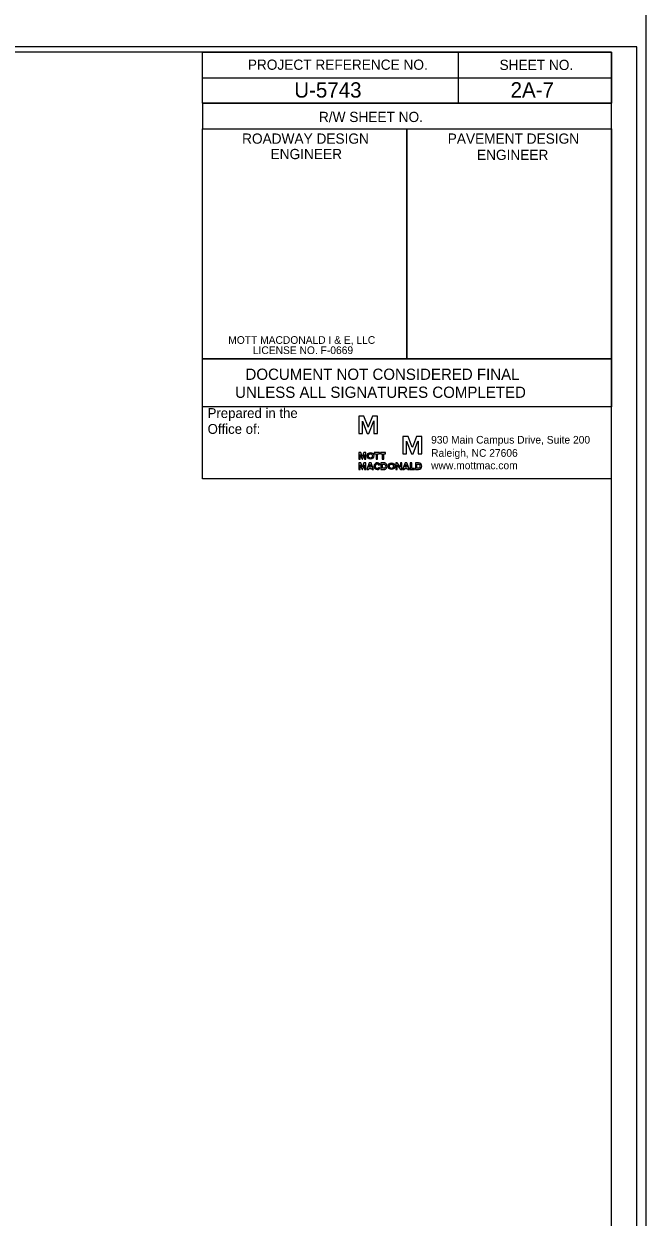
# Model space of a CAD drawing. Extents: x 1901670 to 1902225, y 193498 to 194278.
# Drawn here: x 1902103.8 to 1902134.2, y 193548.5 to 193606.9 of the extents above; entities that cross this region are included whole.
import ezdxf

# ---------------------------------------------------------------- set-up
doc = ezdxf.new("R2010")
doc.units = 0
for name, color, linetype in [('Old_Level_2', 7, 'Continuous'), ('Old_Level_42', 7, 'Continuous'), ('Old_Level_45', 7, 'Continuous'), ('Sheet Border Standard 30in CELL', 7, 'Continuous'), ('Sheet Data Field CELL', 7, 'Continuous'), ('Sheet Plot Border Inside CELL', 7, 'Continuous'), ('Sheet Plot Border Outside CELL', 7, 'Continuous'), ('Sheet Sticker Exception Certification CELL', 7, 'Continuous')]:
    doc.layers.add(name, color=color, linetype=linetype)

msp = doc.modelspace()

# ---------------------------------------------------------------- linework, layer by layer
at = {"layer": 'Old_Level_2'}
for p, q in [((1902120.437, 193587.699), (1902120.185, 193587.699)), ((1902120.185, 193587.699), (1902120.185, 193586.849)), ((1902120.642, 193587.174), (1902120.437, 193587.699)), ((1902120.853, 193587.699), (1902120.647, 193587.174)), ((1902121.105, 193587.699), (1902120.853, 193587.699)), ((1902121.105, 193586.849), (1902121.105, 193587.699)), ((1902120.364, 193586.849), (1902120.364, 193587.46)), ((1902120.364, 193587.46), (1902120.366, 193587.46)), ((1902120.366, 193587.46), (1902120.606, 193586.849)), ((1902120.642, 193587.166), (1902120.642, 193587.174)), ((1902120.647, 193587.166), (1902120.642, 193587.166)), ((1902120.647, 193587.174), (1902120.647, 193587.166)), ((1902120.684, 193586.849), (1902120.923, 193587.463)), ((1902120.923, 193587.463), (1902120.925, 193587.463)), ((1902120.925, 193587.463), (1902120.925, 193586.849)), ((1902120.185, 193586.849), (1902120.364, 193586.849)), ((1902120.606, 193586.849), (1902120.684, 193586.849)), ((1902120.925, 193586.849), (1902121.105, 193586.849)), ((1902122.598, 193586.709), (1902122.346, 193586.709)), ((1902122.346, 193586.709), (1902122.346, 193585.859)), ((1902122.525, 193585.859), (1902122.525, 193586.47)), ((1902122.525, 193586.47), (1902122.528, 193586.47)), ((1902122.528, 193586.47), (1902122.767, 193585.859)), ((1902122.803, 193586.184), (1902122.598, 193586.709)), ((1902123.014, 193586.709), (1902122.809, 193586.184)), ((1902122.845, 193585.859), (1902123.084, 193586.472)), ((1902123.266, 193586.709), (1902123.014, 193586.709)), ((1902123.084, 193586.472), (1902123.087, 193586.472)), ((1902123.087, 193586.472), (1902123.087, 193585.859)), ((1902123.266, 193585.859), (1902123.266, 193586.709)), ((1902120.281, 193585.919), (1902120.185, 193585.919)), ((1902120.185, 193585.919), (1902120.185, 193585.594)), ((1902120.252, 193585.594), (1902120.252, 193585.828)), ((1902120.252, 193585.828), (1902120.255, 193585.828)), ((1902120.252, 193585.828), (1902120.255, 193585.828)), ((1902120.255, 193585.828), (1902120.346, 193585.594)), ((1902120.361, 193585.716), (1902120.281, 193585.919)), ((1902120.442, 193585.919), (1902120.361, 193585.716)), ((1902120.377, 193585.594), (1902120.468, 193585.828)), ((1902120.538, 193585.919), (1902120.442, 193585.919)), ((1902120.468, 193585.828), (1902120.47, 193585.828)), ((1902120.468, 193585.828), (1902120.47, 193585.828)), ((1902120.468, 193585.828), (1902120.47, 193585.828)), ((1902120.47, 193585.828), (1902120.471, 193585.594)), ((1902120.538, 193585.594), (1902120.538, 193585.919)), ((1902120.538, 193585.594), (1902120.538, 193585.919)), ((1902122.346, 193585.859), (1902122.525, 193585.859)), ((1902122.767, 193585.859), (1902122.845, 193585.859)), ((1902122.803, 193586.176), (1902122.803, 193586.184)), ((1902122.809, 193586.176), (1902122.803, 193586.176)), ((1902122.809, 193586.184), (1902122.809, 193586.176)), ((1902123.087, 193585.859), (1902123.266, 193585.859)), ((1902120.185, 193585.594), (1902120.252, 193585.594)), ((1902120.281, 193585.414), (1902120.185, 193585.414)), ((1902120.185, 193585.414), (1902120.185, 193585.089)), ((1902120.252, 193585.089), (1902120.252, 193585.323)), ((1902120.252, 193585.323), (1902120.255, 193585.323)), ((1902120.255, 193585.323), (1902120.346, 193585.089)), ((1902120.361, 193585.211), (1902120.281, 193585.414)), ((1902120.346, 193585.594), (1902120.377, 193585.594)), ((1902120.442, 193585.414), (1902120.361, 193585.211)), ((1902120.377, 193585.089), (1902120.468, 193585.323)), ((1902120.538, 193585.414), (1902120.442, 193585.414)), ((1902120.468, 193585.323), (1902120.47, 193585.323)), ((1902120.47, 193585.323), (1902120.471, 193585.089)), ((1902120.471, 193585.594), (1902120.538, 193585.594)), ((1902120.538, 193585.089), (1902120.538, 193585.414)), ((1902121.221, 193585.156), (1902121.164, 193585.184)), ((1902121.221, 193585.156), (1902121.164, 193585.184)), ((1902121.172, 193585.308), (1902121.229, 193585.335)), ((1902121.172, 193585.308), (1902121.229, 193585.334)), ((1902121.422, 193585.414), (1902121.274, 193585.414)), ((1902121.274, 193585.414), (1902121.274, 193585.246)), ((1902121.274, 193585.246), (1902121.274, 193585.089)), ((1902121.341, 193585.152), (1902121.341, 193585.354)), ((1902121.341, 193585.354), (1902121.422, 193585.354)), ((1902121.422, 193585.152), (1902121.341, 193585.152)), ((1902122.955, 193585.414), (1902122.955, 193585.414)), ((1902123.104, 193585.414), (1902122.955, 193585.414)), ((1902122.955, 193585.414), (1902122.955, 193585.246)), ((1902122.955, 193585.246), (1902122.955, 193585.089)), ((1902123.023, 193585.152), (1902123.023, 193585.354)), ((1902123.023, 193585.354), (1902123.104, 193585.354)), ((1902123.104, 193585.152), (1902123.023, 193585.152)), ((1902123.104, 193585.352), (1902123.104, 193585.352)), ((1902120.185, 193585.089), (1902120.252, 193585.089)), ((1902120.346, 193585.089), (1902120.377, 193585.089)), ((1902120.471, 193585.089), (1902120.538, 193585.089)), ((1902121.274, 193585.089), (1902121.422, 193585.089)), ((1902122.955, 193585.089), (1902123.104, 193585.089))]:
    msp.add_line(p, q, dxfattribs=at)
for points in [[(1902120.946, 193585.859), (1902121.04, 193585.859), (1902121.04, 193585.594), (1902121.11, 193585.594), (1902121.11, 193585.859), (1902121.204, 193585.859), (1902121.204, 193585.919), (1902120.946, 193585.919), (1902120.946, 193585.859)], [(1902121.245, 193585.859), (1902121.339, 193585.859), (1902121.339, 193585.594), (1902121.409, 193585.594), (1902121.409, 193585.859), (1902121.502, 193585.859), (1902121.502, 193585.919), (1902121.245, 193585.919), (1902121.245, 193585.859)], [(1902120.577, 193585.089), (1902120.655, 193585.089), (1902120.676, 193585.144), (1902120.816, 193585.144), (1902120.837, 193585.089), (1902120.912, 193585.089), (1902120.788, 193585.414), (1902120.702, 193585.414), (1902120.577, 193585.089)], [(1902120.694, 193585.204), (1902120.746, 193585.344), (1902120.798, 193585.204), (1902120.694, 193585.204)], [(1902122.069, 193585.3), (1902122.072, 193585.3), (1902122.228, 193585.089), (1902122.293, 193585.089), (1902122.293, 193585.414), (1902122.225, 193585.414), (1902122.225, 193585.209), (1902122.072, 193585.414), (1902122.004, 193585.414), (1902122.004, 193585.089), (1902122.069, 193585.089), (1902122.069, 193585.3)], [(1902122.334, 193585.089), (1902122.412, 193585.089), (1902122.433, 193585.144), (1902122.573, 193585.144), (1902122.594, 193585.089), (1902122.67, 193585.089), (1902122.545, 193585.414), (1902122.459, 193585.414), (1902122.334, 193585.089)], [(1902122.451, 193585.204), (1902122.503, 193585.344), (1902122.555, 193585.204), (1902122.451, 193585.204)], [(1902122.917, 193585.089), (1902122.917, 193585.147), (1902122.776, 193585.147), (1902122.776, 193585.414), (1902122.709, 193585.414), (1902122.709, 193585.089), (1902122.917, 193585.089)], [(1902122.917, 193585.089), (1902122.917, 193585.147), (1902122.776, 193585.147), (1902122.776, 193585.414), (1902122.709, 193585.414), (1902122.709, 193585.089), (1902122.917, 193585.09), (1902122.917, 193585.147)]]:
    msp.add_lwpolyline(points, dxfattribs=at)
msp.add_arc((1902123.104, 193585.252), 0.162, 270, 90, dxfattribs=at)
for centre, major_axis, ratio in [((1902120.759, 193585.756), (0, 0.162), 0.993118), ((1902120.759, 193585.756), (0, 0.106), 0.916103), ((1902121.786, 193585.252), (0, 0.162), 0.993118), ((1902121.786, 193585.252), (0, 0.106), 0.916103)]:
    msp.add_ellipse(centre, major_axis=major_axis, ratio=ratio, dxfattribs=at)
for centre, major_axis, ratio, start_param, end_param in [((1902121.09, 193585.252), (0, 0.162), 0.993118, 5.246647, 10.366427), ((1902121.09, 193585.252), (0, 0.162), 0.993118, 5.246647, 10.366427), ((1902121.09, 193585.252), (0, 0.106), 0.916103, 5.276876, 9.424778), ((1902121.09, 193585.252), (0, 0.106), 0.916103, 5.276876, 10.296021), ((1902121.09, 193585.252), (0, 0.106), 0.916103, 3.141593, 4.012835), ((1902121.422, 193585.252), (0, -0.162), 0.930276, 0, 3.141593), ((1902121.422, 193585.253), (0, -0.101), 0.900832, 0, 3.141593), ((1902123.104, 193585.253), (0, -0.101), 0.900832, 0, 3.141593)]:
    msp.add_ellipse(centre, major_axis=major_axis, ratio=ratio, start_param=start_param, end_param=end_param, dxfattribs=at)
at = {"layer": 'Old_Level_42'}
msp.add_lwpolyline([(1902132.544, 193584.629), (1902112.539, 193584.629), (1902112.539, 193588.159)], dxfattribs=at)
at = {"layer": 'Sheet Border Standard 30in CELL'}
for p, q in [((1902125.044, 193605.509), (1902125.044, 193603.009)), ((1902112.539, 193604.259), (1902132.544, 193604.259)), ((1902112.539, 193603.009), (1902132.544, 193603.009)), ((1902112.539, 193603.009), (1902112.539, 193601.759)), ((1902112.539, 193603.009), (1902132.544, 193603.009)), ((1902122.544, 193601.759), (1902122.544, 193590.514))]:
    msp.add_line(p, q, dxfattribs=at)
for points in [[(1902132.544, 193605.514), (1901982.544, 193605.514), (1901982.544, 193500.514), (1902132.544, 193500.514)], [(1902112.539, 193605.514), (1902132.544, 193605.514), (1902132.544, 193603.009), (1902112.539, 193603.009)], [(1902112.539, 193601.759), (1902122.544, 193601.759), (1902122.544, 193590.509), (1902112.539, 193590.509)], [(1902122.544, 193601.759), (1902132.544, 193601.759), (1902132.544, 193590.509), (1902122.544, 193590.509)]]:
    msp.add_lwpolyline(points, close=True, dxfattribs=at)
at = {"layer": 'Sheet Plot Border Inside CELL'}
msp.add_lwpolyline([(1902133.794, 193605.769), (1901967.144, 193605.769), (1901967.144, 193500.259), (1902133.794, 193500.259)], close=True, dxfattribs=at)
at = {"layer": 'Sheet Plot Border Outside CELL'}
msp.add_lwpolyline([(1902134.244, 193608.014), (1901965.844, 193608.014), (1901965.844, 193498.014), (1902134.244, 193498.014)], close=True, dxfattribs=at)
at = {"layer": 'Sheet Sticker Exception Certification CELL'}
for p, q in [((1902112.539, 193588.159), (1902112.539, 193590.509)), ((1902112.539, 193590.509), (1902132.542, 193590.509)), ((1902132.542, 193590.508), (1902132.542, 193588.158)), ((1902132.542, 193588.159), (1902112.539, 193588.159))]:
    msp.add_line(p, q, dxfattribs=at)

# ---------------------------------------------------------------- texts
at = {"layer": 'Old_Level_2'}
for s, height, p in [('Prepared in the ', 0.48186, (1902112.794, 193587.609)), ('Office of:', 0.4819, (1902112.794, 193586.834))]:
    msp.add_text(s, height=height, dxfattribs=at).set_placement(p)
for s, p in [('930 Main Campus Drive, Suite 200', (1902123.726, 193586.357)), ('Raleigh, NC 27606', (1902123.726, 193585.712)), ('www.mottmac.com ', (1902123.726, 193585.103))]:
    msp.add_text(s, height=0.375, rotation=360, dxfattribs=at).set_placement(p)
at = {"layer": 'Old_Level_45'}
for s, p in [('MOTT MACDONALD I & E, LLC', (1902113.803, 193591.238)), (' LICENSE NO. F-0669', (1902114.866, 193590.738))]:
    msp.add_text(s, height=0.375, rotation=360, dxfattribs=at).set_placement(p)
at = {"layer": 'Sheet Border Standard 30in CELL'}
for s, height, p in [('PROJECT REFERENCE NO.', 0.50001, (1902114.759, 193604.644)), ('SHEET NO.', 0.5, (1902127.074, 193604.634)), ('R/W SHEET NO.', 0.50001, (1902118.239, 193602.089)), ('ROADWAY DESIGN', 0.50001, (1902114.479, 193601.029)), ('PAVEMENT DESIGN', 0.50001, (1902124.538, 193601.029)), ('ENGINEER', 0.5, (1902115.874, 193600.274)), ('ENGINEER', 0.5, (1902125.969, 193600.234))]:
    msp.add_text(s, height=height, dxfattribs=at).set_placement(p)
at = {"layer": 'Sheet Data Field CELL'}
for s, p in [('U-5743', (1902117.032, 193603.284)), ('2A-7', (1902127.614, 193603.289))]:
    msp.add_text(s, height=0.75, dxfattribs=at).set_placement(p)
at = {"layer": 'Sheet Sticker Exception Certification CELL'}
for s, p in [('DOCUMENT NOT CONSIDERED FINAL', (1902114.646, 193589.475)), ('UNLESS ALL SIGNATURES COMPLETED', (1902114.139, 193588.595))]:
    msp.add_text(s, height=0.55, dxfattribs=at).set_placement(p)

doc.saveas('drawing.dxf')
